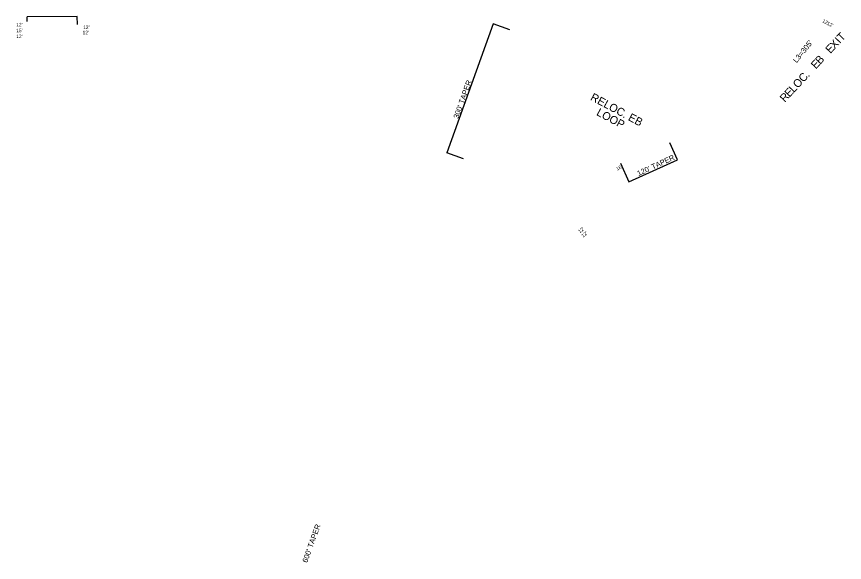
# Model space of a CAD drawing. Extents: x 1938746 to 1943895, y 778846 to 782535.
# Drawn here: x 1939601 to 1941463, y 778846 to 780075 of the extents above; entities that cross this region are included whole.
import ezdxf

# ---------------------------------------------------------------- set-up
doc = ezdxf.new("R2010")
doc.units = 0
doc.layers.add('RD_PD_Final_TX', color=7, linetype='Continuous')
doc.layers.add('RD_TX_RoadID', color=7, linetype='Continuous')

msp = doc.modelspace()

# ---------------------------------------------------------------- linework, layer by layer
at = {"layer": 'RD_PD_Final_TX'}
for p, q in [((1939737.6, 780074.9), (1939624.6, 780074)), ((1939624.7, 780063.5), (1939624.6, 780074)), ((1939737.7, 780056.9), (1939737.6, 780074.9)), ((1940672.4, 780058.5), (1940568.5, 779768.6)), ((1940710, 780045), (1940672.4, 780058.5)), ((1941087.4, 779752.8), (1941070.1, 779791)), ((1940606.2, 779755.1), (1940568.5, 779768.6)), ((1940959.1, 779745.2), (1940978, 779703.3)), ((1940978, 779703.3), (1941087.4, 779752.8))]:
    msp.add_line(p, q, dxfattribs=at)

# ---------------------------------------------------------------- texts
for s, height, rotation, p in [("12'", 8, 0.7793, (1939600.1, 780052.6)), ("12'", 8, 332.1494, (1941412.1, 780062.6)), ("12'", 8, 332.1494, (1941422.3, 780057)), ("15'", 8, 0.7793, (1939600.1, 780039.6)), ("12'", 8, 0.7793, (1939749.4, 780034.8)), ("12'", 8, 0.7793, (1939750.7, 780046.8)), ("12'", 8, 0.7793, (1939600.1, 780026.3)), ("L3=305'", 12, 51.0994, (1941355.1, 779969.6)), ("300' TAPER", 12, 70.3766, (1940594.2, 779844)), ("120' TAPER", 12, 24.7453, (1940999.6, 779715.6)), ("16'", 8, 27.2633, (1940951.5, 779727.8)), ("12'", 8, 38.5136, (1940867.6, 779587)), ("12'", 8, 38.5136, (1940874.9, 779577.3)), ("600' TAPER", 12, 70.3766, (1940254.4, 778844.7))]:
    msp.add_text(s, height=height, rotation=rotation, dxfattribs=at).set_placement(p)
at = {"layer": 'RD_TX_RoadID'}
for s, rotation, p in [('T', 46.8807, (1941456.8, 780018.1)), ('X', 46.8807, (1941440.6, 780000.8)), ('I', 46.8807, (1941452.1, 780013.1)), ('E', 46.8807, (1941431, 779990.5)), ('B', 46.8807, (1941408, 779966)), ('E', 46.8807, (1941398.4, 779955.7)), ('C', 46.8807, (1941370.4, 779925.8)), ('O', 46.8807, (1941357.8, 779912.4)), ('.', 46.8807, (1941381.6, 779937.8)), ('E', 46.8807, (1941339, 779892.3)), ('L', 46.8807, (1941348.7, 779902.6)), ('RELOC. EB ', 331.8238, (1940889.8, 779887.9)), ('R', 46.8807, (1941328.4, 779881)), ('LOOP', 331.8238, (1940903.4, 779853.8))]:
    msp.add_text(s, height=18, rotation=rotation, dxfattribs=at).set_placement(p)

doc.saveas('drawing.dxf')
